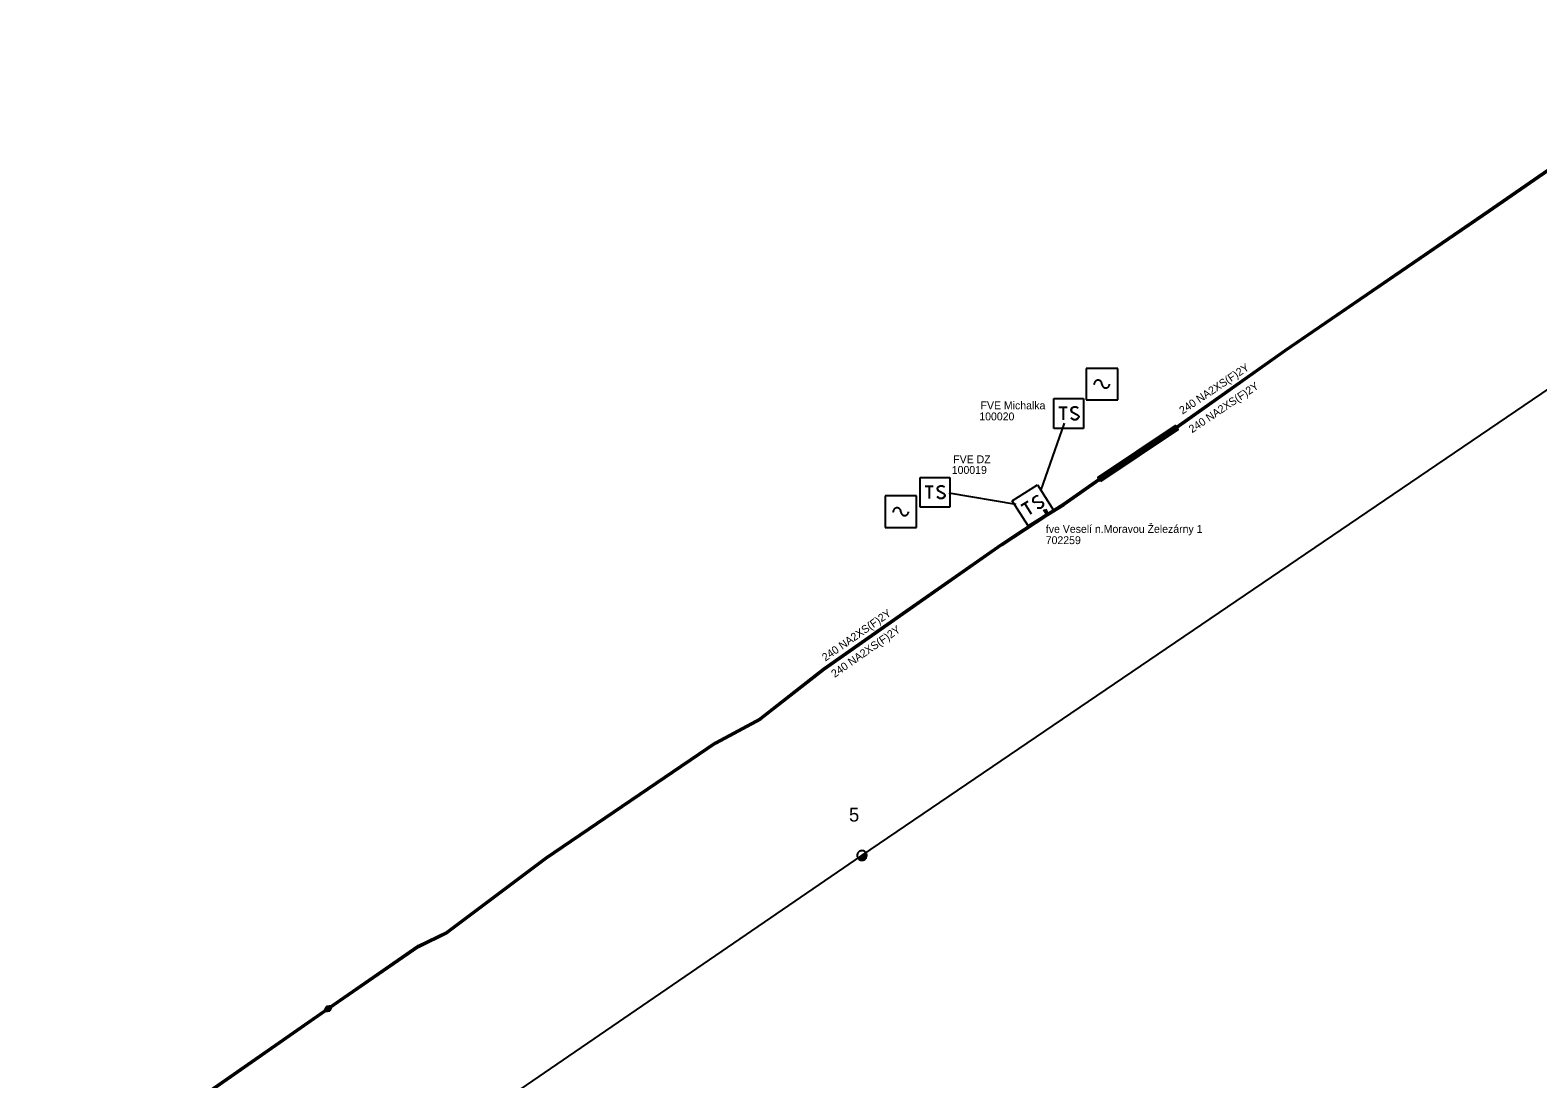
# Model space of a CAD drawing. Extents: x -545588 to -543214, y -1196037 to -1194452.
# Drawn here: x -545008.8 to -544817.1, y -1194764.6 to -1194631.3 of the extents above; entities that cross this region are included whole.
import ezdxf

# ---------------------------------------------------------------- set-up
doc = ezdxf.new("R2010")
doc.units = 0
for name, color, linetype in [('DOPLŇ_POPISY', 7, 'Continuous'), ('ELE_EON', 7, 'Continuous'), ('ELE_EON_POPIS', 7, 'Continuous'), ('POL_ZNAČKA_PRACOVNÍ', 7, 'Continuous'), ('SDEL_EON_POPIS', 7, 'Continuous'), ('Vrstva 19', 7, 'Continuous'), ('Vrstva 20', 7, 'Continuous'), ('Vrstva 25', 7, 'Continuous'), ('Vrstva 26', 7, 'Continuous'), ('Vrstva 27', 7, 'Continuous'), ('Vrstva 34', 7, 'Continuous'), ('ZP_EON', 7, 'Continuous'), ('ZP_EON_POPIS', 7, 'Continuous')]:
    doc.layers.add(name, color=color, linetype=linetype)

# ---------------------------------------------------------------- blocks, each defined once
blk = doc.blocks.new('VN440')
at = {"layer": 'ELE_EON_POPIS'}
for points in [[(1.22, 0), (1.21, 0.13), (1.19, 0.25), (1.16, 0.38), (1.11, 0.5), (1.05, 0.61), (0.98, 0.72), (0.9, 0.82), (0.81, 0.91), (0.71, 0.99), (0.6, 1.06), (0.49, 1.12), (0.37, 1.16), (0.25, 1.2), (0.12, 1.22), (-0.01, 1.22), (-0.14, 1.22), (-0.26, 1.2), (-0.39, 1.16), (-0.51, 1.12), (-0.62, 1.06), (-0.73, 0.99), (-0.83, 0.91), (-0.92, 0.82), (-1, 0.72), (-1.07, 0.61), (-1.13, 0.5), (-1.18, 0.38), (-1.21, 0.25), (-1.23, 0.13), (-1.24, 0), (-1.23, -0.13), (-1.21, -0.26), (-1.18, -0.38), (-1.13, -0.5), (-1.07, -0.62), (-1, -0.73), (-0.92, -0.83), (-0.83, -0.92), (-0.73, -1), (-0.62, -1.07), (-0.51, -1.13), (-0.39, -1.17), (-0.26, -1.2), (-0.14, -1.23), (-0.01, -1.23), (0.12, -1.23), (0.25, -1.2), (0.37, -1.17), (0.49, -1.13), (0.6, -1.07), (0.71, -1), (0.81, -0.92), (0.9, -0.83), (0.98, -0.73), (1.05, -0.62), (1.11, -0.5), (1.16, -0.38), (1.19, -0.26), (1.21, -0.13), (1.22, 0)], [(-1.24, 0), (1.22, 0)], [(-1.18, -0.34), (1.1, -0.34)], [(-1.01, -0.63), (0.97, -0.63)], [(-0.74, -0.92), (0.68, -0.92)]]:
    blk.add_lwpolyline(points, dxfattribs=at)
blk = doc.blocks.new('VN870')
at = {"layer": 'SDEL_EON_POPIS'}
for points in [[(0, -0.25), (0.5, 0), (0, 0.25), (-0.5, 0), (0, -0.25)], [(0.37, 0), (0, 0.19), (-0.36, 0), (0, -0.19), (0.37, 0)], [(0.24, 0), (0, 0.12), (-0.25, 0), (0, -0.12), (0.24, 0)], [(0.12, 0), (0, 0.06), (-0.13, 0), (0, -0.06), (0.12, 0)]]:
    blk.add_lwpolyline(points, dxfattribs=at)
blk = doc.blocks.new('VN740')
at = {"layer": 'ELE_EON'}
for points in [[(2, 2), (-2, 2)], [(-2, 2), (-2, -2)], [(2, -2), (2, 2)], [(0, 0), (0, 0.05), (-0.01, 0.1), (-0.02, 0.15), (-0.04, 0.2), (-0.06, 0.24), (-0.09, 0.29), (-0.12, 0.33), (-0.16, 0.36), (-0.2, 0.4), (-0.24, 0.42), (-0.29, 0.45), (-0.34, 0.47), (-0.38, 0.48), (-0.44, 0.49), (-0.49, 0.49), (-0.54, 0.49), (-0.59, 0.48), (-0.64, 0.47), (-0.69, 0.45), (-0.73, 0.43), (-0.77, 0.4), (-0.81, 0.37), (-0.85, 0.33), (-0.88, 0.29), (-0.91, 0.25), (-0.93, 0.2), (-0.95, 0.16), (-0.97, 0.11), (-0.97, 0.06), (-0.98, 0), (-0.98, 0)], [(0, 0), (0, -0.05), (0.01, -0.1), (0.02, -0.15), (0.04, -0.2), (0.06, -0.24), (0.09, -0.28), (0.12, -0.32), (0.15, -0.36), (0.19, -0.39), (0.23, -0.42), (0.28, -0.44), (0.32, -0.46), (0.37, -0.48), (0.42, -0.49), (0.47, -0.49), (0.52, -0.49), (0.57, -0.48), (0.62, -0.47), (0.67, -0.45), (0.71, -0.43), (0.75, -0.4), (0.79, -0.37), (0.83, -0.34), (0.86, -0.3), (0.89, -0.26), (0.91, -0.21), (0.93, -0.17), (0.95, -0.12), (0.96, -0.07), (0.96, -0.02), (0.96, -0.02)], [(-2, -2), (2, -2)]]:
    blk.add_lwpolyline(points, dxfattribs=at)
blk = doc.blocks.new('VN640')
at = {"layer": 'ZP_EON_POPIS'}
for points in [[(-1.89, 1.89), (1.89, 1.89)], [(-1.89, -1.89), (-1.89, 1.89)], [(-1.26, 0.79), (-0.22, 0.79)], [(-0.73, 0.79), (-0.73, -0.79)], [(1.2, 0.66), (0.94, 0.79), (0.66, 0.79), (0.41, 0.66), (0.28, 0.47), (0.28, 0.41), (0.41, 0.22), (1.13, -0.16), (1.26, -0.32), (1.26, -0.47), (1.13, -0.66), (0.91, -0.79), (0.63, -0.79), (0.5, -0.73), (0.28, -0.6)], [(1.89, 1.89), (1.89, -1.89)], [(1.89, -1.89), (-1.89, -1.89)]]:
    blk.add_lwpolyline(points, dxfattribs=at)

msp = doc.modelspace()

# ---------------------------------------------------------------- linework, layer by layer
at = {"layer": 'ELE_EON'}
msp.add_lwpolyline([(-545096.16, -1194848.04), (-545075.95, -1194854.58), (-545032.81, -1194825.14), (-544993.69, -1194798.32), (-544903.01, -1194736.22), (-544804.37, -1194669.21), (-544702.68, -1194600.1), (-544611.95, -1194519.78), (-544514.29, -1194451.62)], dxfattribs=at)
at = {"layer": 'Vrstva 20'}
msp.add_lwpolyline([(-544872.66, -1194688.66), (-544873, -1194688.16), (-544863.15, -1194681.54), (-544862.81, -1194682.04)], close=True, dxfattribs=at)
at = {"layer": 'ZP_EON'}
for points in [[(-544879.69, -1194692.19), (-544879.38, -1194692.72), (-544877.42, -1194691.5), (-544872.89, -1194688.33), (-544863.04, -1194681.71), (-544849.25, -1194671.95), (-544823.31, -1194654.21), (-544796.7, -1194635.8), (-544769.45, -1194617.2), (-544745.44, -1194600.7), (-544712.88, -1194578.62), (-544686.33, -1194560.51), (-544663.49, -1194544.51), (-544638.43, -1194527.34), (-544613.5, -1194510.21), (-544588.16, -1194493), (-544563.72, -1194476.13), (-544542.28, -1194461.2), (-544536.69, -1194457.31), (-544535.63, -1194456.59)], [(-545017.49, -1194788.17), (-544994.72, -1194772.48), (-544991.46, -1194771.51), (-544987.68, -1194767.54), (-544970.83, -1194755.78), (-544959.36, -1194747.87), (-544955.67, -1194746.06), (-544943.12, -1194736.64), (-544921.55, -1194722), (-544915.88, -1194718.94), (-544907.79, -1194712.62), (-544897.27, -1194705.22), (-544885.19, -1194696.78), (-544879.36, -1194692.94), (-544877.31, -1194691.66), (-544872.77, -1194688.49), (-544862.92, -1194681.87), (-544849.13, -1194672.11), (-544823.19, -1194654.37), (-544796.58, -1194635.96)], [(-544880.28, -1194689.86), (-544877.25, -1194681.26)], [(-544883.39, -1194691.6), (-544891.93, -1194690.16)], [(-545233.41, -1194894.88), (-545178.88, -1194890.69), (-545165.68, -1194889.55), (-545162.68, -1194888.62), (-545146.55, -1194877.89), (-545122.2, -1194861.06), (-545095.47, -1194842.73), (-545060.25, -1194817.94), (-545034.96, -1194800.14), (-545017.61, -1194788.01), (-544994.8, -1194772.3), (-544991.56, -1194771.33), (-544987.81, -1194767.38), (-544970.95, -1194755.62), (-544959.46, -1194747.69), (-544955.77, -1194745.88), (-544943.24, -1194736.48), (-544921.65, -1194721.82), (-544915.98, -1194718.78), (-544907.91, -1194712.46), (-544897.39, -1194705.06), (-544885.31, -1194696.62), (-544879.55, -1194692.83), (-544879.87, -1194692.29)]]:
    msp.add_lwpolyline(points, dxfattribs=at)

# ---------------------------------------------------------------- block references
at = {"layer": 'DOPLŇ_POPISY', "xscale": 0.5, "yscale": 0.5, "rotation": 34.40455542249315}
msp.add_blockref('VN440', (-544903.01, -1194736.22), dxfattribs=at)
at = {"layer": 'Vrstva 19'}
for p, rotation in [((-544970.95, -1194755.62), 34.91301949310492), ((-544970.83, -1194755.78), 34.91111663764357)]:
    msp.add_blockref('VN870', p, dxfattribs=dict(at, rotation=rotation))
at = {"layer": 'Vrstva 25'}
for p in [(-544876.71, -1194680.02), (-544893.73, -1194690.03)]:
    msp.add_blockref('VN640', p, dxfattribs=at)
at = {"layer": 'Vrstva 25', "rotation": 32.363291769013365}
msp.add_blockref('VN640', (-544881.28, -1194691.71), dxfattribs=at)
at = {"layer": 'Vrstva 34'}
for p in [(-544872.49, -1194676.28), (-544898.06, -1194692.51)]:
    msp.add_blockref('VN740', p, dxfattribs=at)

# ---------------------------------------------------------------- texts
at = {"layer": 'POL_ZNAČKA_PRACOVNÍ'}
msp.add_text('5', height=1.75, dxfattribs=at).set_placement((-544904.66, -1194731.91))
at = {"layer": 'Vrstva 26'}
for s, p in [('100020', (-544888.09, -1194680.89)), ('100019', (-544891.59, -1194687.7)), ('702259', (-544879.64, -1194696.63))]:
    msp.add_text(s, height=1, dxfattribs=at).set_placement(p)
at = {"layer": 'Vrstva 27'}
for s, p in [('FVE Michalka', (-544887.93, -1194679.49)), ('FVE DZ', (-544891.4, -1194686.34)), ('fve Veselí n.Moravou Železárny 1', (-544879.62, -1194695.2))]:
    msp.add_text(s, height=1, dxfattribs=at).set_placement(p)
at = {"layer": 'ZP_EON_POPIS'}
for rotation, p in [(33.904, (-544862.24, -1194680.17)), (33.904, (-544861.02, -1194682.54)), (34.942, (-544907.66, -1194711.57)), (34.94, (-544906.49, -1194713.65))]:
    msp.add_text('240 NA2XS(F)2Y', height=1, rotation=rotation, dxfattribs=at).set_placement(p)

doc.saveas('drawing.dxf')
